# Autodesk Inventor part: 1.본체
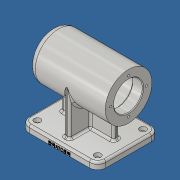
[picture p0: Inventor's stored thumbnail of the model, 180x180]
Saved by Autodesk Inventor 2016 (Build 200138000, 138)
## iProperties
Created: 2020-10
Part Number: 1.본체
Material: 알루미늄 6061
Document SubType Name: Modeling
Designer: 605-11
Density: 2.7 g/cm^3
Appearance: 알루미늄 - 평지
Mass: 1026.28 g
Surface Area: 757.984 cm^2
Volume: 380.103 cm^3
Author: 605-11
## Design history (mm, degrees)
sketch "스케치2"
  geometry: L1 (-56, 0)-(56, 0); L2 (-56, 0)-(-56, 34); L3 (-56, 34)-(56, 34); L4 (56, 34)-(56, 0); L5 (-50, 0)-(-50, 10.5); L6 (-50, 10.5)-(-47, 10.5); L7 (-47, 10.5)-(-47, 16); L8 (-47, 16)-(-43, 16); L9 (-43, 16)-(-43, 17.5); L10 (-43, 17.5)-(-25, 17.5); L11 (-25, 17.5)-(-25, 21); L12 (-25, 21)-(-13, 21); L13 (-13, 21)-(-13, 24); L14 (-13, 24)-(41, 24); L15 (41, 24)-(41, 21); L16 (41, 21)-(56, 21); 2 further points
  constraints: 32 end point, 13 perpendicular, 2 point on line, 2 vertical, 1 coincident, 1 horizontal, 1 midpoint
  dimensions: "d23" = 21 diameter of L6 L1; "d24" = 32 diameter of L8 L1; "d25" = 35 diameter of L10 L1; "d26" = 42 diameter of L12 L1; "d27" = 48 diameter of L14 L1; "d28" = 42 diameter of L16 L1; "d29" = 68 diameter of L3 L1; "d30" = 112 distance between parallel lines of L4 L2; "d31" = 3 distance between parallel lines of L7 L5; "d32" = 15 distance between parallel lines of L4 L15; "d33" = 54 distance between parallel lines of L15 L13; "d34" = 4 distance between parallel lines of L9 L7; "d35" = 18 distance between parallel lines of L11 L9; "d36" = 12 distance between parallel lines of L13 L11
revolve "회전2" sketch "스케치2" stored, may be unused: angle "d37" = 90 deg
fillet "모깎기1" dims "d38" = 10
fillet "모깎기2" dims "d39" = 3
fillet "모깎기3" dims "d40" = 0.3
fillet "모깎기4" dims "d41" = 3
chamfer "모따기1" distance "d42" = 1; stored, may be unused: second distance "d43" = 2, angle "d44" = 45 deg
node "작업 평면1"
sketch "스케치3"
  geometry: L1 (56, 45)-(-56, 45); L2 (-56, 45)-(-56, -45); L3 (-56, -45)-(56, -45); L4 (56, -45)-(56, 45); L5 (56, 45)-(-56, -45); L6 (-56, 45)-(56, -45); 1 further point
  constraints: 12 end point, 2 midpoint, 2 parallel, 1 horizontal, 1 perpendicular
  dimensions: "d46" = 112 distance of L2.end L3.end; "d47" = 90 distance of L3.end L1.start
extrude "돌출1" join sketch "스케치3" distance "d48" = 10; taper "d49" = 0 deg
sketch "스케치4"
  geometry: L1 (38, 4)-(-38, 4); L2 (-38, 4)-(-38, -4); L3 (-38, -4)-(38, -4); L4 (38, -4)-(38, 4); L5 (38, 4)-(-38, -4); L6 (-38, 4)-(38, -4); L7 (4, 34)-(-4, 34); L8 (-4, 34)-(-4, -34); L9 (-4, -34)-(4, -34); L10 (4, -34)-(4, 34); L11 (4, 34)-(-4, -34); L12 (-4, 34)-(4, -34); L13 (-56, -45)-(56, -45) reference; L14 (-56, 45)-(-56, -45) reference; L15 (56, 45)-(-56, 45) reference; L16 (56, -45)-(56, 45) reference; 1 further point
  constraints: 24 end point, 4 midpoint, 4 parallel, 2 horizontal, 2 perpendicular
  dimensions: "d50" = 8 distance between parallel lines of L3 L1; "d51" = 8 distance of L7.start L7.end; "d52" = 18 distance between parallel lines of L16 L4; "d54" = 68 distance between parallel lines of L9 L7
extrude "돌출2" join sketch "스케치4" stored distance "d55" = 10; taper "d56" = 0 deg
fillet "모깎기5" dims "d57" = 3
fillet "모깎기7" dims "d59" = 12
sketch "스케치5"
  geometry: L1 (44, 45)-(-44, 45) reference; L2 (56, -33)-(56, 33) reference; L3 (-44, -45)-(44, -45) reference; L4 (-56, 33)-(-56, -33) reference; A1 r 12 centre (-44, 33) between (-44, 45) and (-56, 33) reference; A2 r 12 centre (44, 33) between (56, 33) and (44, 45) reference; A3 r 12 centre (44, -33) between (44, -45) and (56, -33) reference; A4 r 12 centre (-44, -33) between (-56, -33) and (-44, -45) reference; 1 further point
hole "구멍1" sketch "스케치5" at (-44, -33), (-44, 33), (44, 33), (44, -33) diameter "d60" = 5.5; stored, may be unused: countersink angle "d64" = 90 deg, drill point angle "d66" = 118 deg; dims "d61" = 6, "d62" = 9.5, "d63" = 5.4, "d65" = 8
fillet "모깎기8" dims "d67" = 3
sketch "스케치6"
  geometry: L1 (0, 0)-(0, 26)
  constraints: 2 end point, 1 vertical
  dimensions: "d68" = 26 distance of L1.start L1.end
hole "구멍2" sketch "스케치6" at (0, 26) diameter "d69" = 3.242; stored, may be unused: countersink angle "d73" = 90 deg, drill point angle "d75" = 118 deg; dims "d70" = 8, "d71" = 9.5, "d72" = 5.4, "d74" = 11
sketch "스케치7"
  geometry: L1 (27.605, 5.402)-(60.788, 5.402); L2 (60.788, 5.402)-(60.788, 0.598); L3 (60.788, 0.598)-(27.605, 0.598); L4 (27.605, 0.598)-(27.605, 5.402); L5 (88, 7)-(100, 7) reference; L6 (88, 7)-(88, 0) reference; L7 (88, 0)-(100, 0) reference; L8 (100, 0)-(100, 7) reference; L9 (27.605, 3)-(44, 3); L10 (44, 0.598)-(44, 3); 1 further point
  constraints: 4 end point, 1 midpoint, 1 perpendicular, 1 point on line, 2 other
  dimensions: "d79" = 56 distance between parallel lines of L8 L10; "d83" = 3 distance between parallel lines of L7 L9
feature "엠보싱1" sketch "스케치7" dims "d23" = 21, "d24" = 32, "d25" = 35, "d26" = 42, "d27" = 48, "d28" = 42, "d29" = 68, "d30" = 112, "d31" = 3, "d32" = 15, "d33" = 54, "d34" = 4, "d35" = 18, "d36" = 12, "d81" = 0.5, "d82" = 0
fillet "모깎기6" dims "d58" = 3
node "솔리드2"
pattern_circular "원형 패턴1" dims angle "d77" = 360 deg
node "투영된 루프1"
node "투영된 루프2"
node "투영된 루프3"
other parameters: "d45" = -74
